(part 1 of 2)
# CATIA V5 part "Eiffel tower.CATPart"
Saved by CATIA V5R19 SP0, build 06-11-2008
Part number: Eiffel tower
Bounding box of the stored display mesh (mm): x -48.5 to 48.5, y -48.5 to 48.5, z 0 to 240.712
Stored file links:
  C:\Documents and Settings\jcerki\Desktop\Eiffel Tower\Eiffel tower.CATPart
  C:\Program Files\Dassault Systemes\B19\intel_a\startup\materials\Catalog.CATMaterial
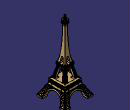
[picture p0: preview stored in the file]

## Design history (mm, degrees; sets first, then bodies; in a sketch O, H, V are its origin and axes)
Sketch1 on xy-plane, origin (0, 0, 0), H (1, 0, 0), V (0, 1, 0)
  line L1 (48.5, 48.5) -> (-48.5, 48.5)
  line L2 (-48.5, 48.5) -> (-48.5, -48.5)
  line L3 (-48.5, -48.5) -> (48.5, -48.5)
  point P4 (48.5, -48.5)
  line L4 (48.5, 48.5) -> (48.5, -48.5)
  point P5 (48.5, -48.5)
  horizontal: L1 H, L3 H
  vertical: L2 V, L4 V
  coincidence: P4 P5
Pad1: profile Sketch1, direction (0, 0, 1), length 6
Sketch2 on Plane2, origin (0, 0, 51.21), H (1, 0, 0), V (0, 1, 0)
  line L1 (27.9, -27.9) -> (27.9, 27.9)
  point P1 (27.9, -27.9)
  point P2 (27.9, 27.9)
  reference projected line E1 (27.9, -27.9) -> (27.9, 27.9) from edge [face of Pad4 from Sketch4.L2 | end face of Pad4]
  reference projected point E2 (27.9, -27.9) from vertex [face of Pad4 from Sketch4.L2 | end face of Pad4 | face of Pad4 from Sketch4.L1]
  reference projected point E3 (27.9, 27.9) from vertex [end face of Pad4 | face of Pad4 from Sketch4.L3 | face of Pad4 from Sketch4.L2]
  line L2 (27.9, -27.9) -> (-27.9, -27.9)
  line L3 (-27.9, -27.9) -> (-27.9, 27.9)
  line L4 (27.9, 27.9) -> (-27.9, 27.9)
  vertical: L1 V, L3 V
  coincidence: L1 E1, P1 E2, P2 E3
  horizontal: L2 H, L4 H
Pad2: profile Sketch2, direction (0, 0, 1), length 1.8
CloseSurface1: CloseElement Join4
Sketch3 on end face of Pad11, origin (0, 0, 230.712), H (1, 0, 0), V (0, 1, 0)
  line L1 (-2.12, -2.12) -> (2.12, -2.12)
  line L2 (2.12, -2.12) -> (2.12, 2.12)
  line L3 (2.12, 2.12) -> (-2.12, 2.12)
  line L4 (-2.12, 2.12) -> (-2.12, -2.12)
  horizontal: L1 H, L3 H
  vertical: L2 V, L4 V
Pad3: profile Sketch3, direction (0, 0, 1), length 10
Sketch4 on Plane1, origin (0, 0, 41.21), H (1, 0, 0), V (0, 1, 0)
  line L1 (-27.9, -27.9) -> (27.9, -27.9)
  line L2 (27.9, -27.9) -> (27.9, 27.9)
  line L3 (27.9, 27.9) -> (-27.9, 27.9)
  line L4 (-27.9, 27.9) -> (-27.9, -27.9)
  horizontal: L1 H, L3 H
  vertical: L2 V, L4 V
Pad4: profile Sketch4, direction (0, 0, 1), length 6.2
Fillet1: radius 0.2, on edge [face of Pad13 from Sketch22.A1 | face of Pad14]; edge [face of Pad14 | face of Pad13 from Sketch22.A1]; edge [face of CircPattern5 | face of CircPattern5] (x6); face of CircPattern3 (x10); edge [face of CircPattern3 | face of CircPattern3]; end face of Pad9 (x4); face of Pad9 from Sketch18.L3; face of Pad9 from Sketch18.L4; face of Pad9 from Sketch18.L1; face of Pad9 from Sketch18.L2; start face of Pad12; end face of Pad8; edge [start face of Pad8 | face of Pad8 from Sketch16.L3]; edge [start face of Pad8 | face of Pad8 from Sketch16.L2]; edge [start face of Pad8 | face of Pad8 from Sketch16.L4]; edge [start face of Pad8 | face of Pad8 from Sketch16.L1]
Body1 (main body)
  Plane1: type Offset, Offset 41.21, RefPlane xy-plane
  Fillet2: radius 1, on end face of Pad1
  AxisSystem1: origin (0, 0, 0), X (1, 0, 0), Y (0, 1, 0), Z (0, 0, 1)
  Plane2: type Offset, Offset 10, RefPlane Plane1
  Line1: type PtPt, SecondPoint vertex [face of Fillet2 | face of Fillet2 | end face of Pad1], FirstPoint vertex [face of Pad4 from Sketch4.L4 | start face of Pad4 | face of Pad4 from Sketch4.L1]
  Line2: type PtPt, SecondPoint vertex [end face of Pad1 | face of Fillet2 | face of Fillet2], FirstPoint vertex [face of Pad4 from Sketch4.L1 | start face of Pad4 | face of Pad4 from Sketch4.L2]
  Line3: type PtPt, SecondPoint vertex [face of Fillet2 | end face of Pad1 | face of Fillet2], FirstPoint vertex [face of Pad4 from Sketch4.L4 | start face of Pad4 | face of Pad4 from Sketch4.L3]
  Line4: type PtPt, SecondPoint vertex [face of Fillet2 | face of Fillet2 | end face of Pad1], FirstPoint vertex [face of Pad4 from Sketch4.L3 | start face of Pad4 | face of Pad4 from Sketch4.L2]
  Fill1: Boundary (edge [start face of Pad4 | face of Pad4 from Sketch4.L3]; Line4; edge [face of Fillet2 | end face of Pad1]; Line3)
  Fill2: Boundary (edge [face of Fillet2 | end face of Pad1]; Line4; edge [start face of Pad4 | face of Pad4 from Sketch4.L2]; Line2)
  Fill3: Boundary (Line2; edge [start face of Pad4 | face of Pad4 from Sketch4.L1]; Line1; edge [face of Fillet2 | end face of Pad1])
  Fill4: Boundary (edge [start face of Pad4 | face of Pad4 from Sketch4.L4]; Line3; edge [face of Fillet2 | end face of Pad1]; Line1)
  Join1: Elements (Fill3; Fill4; Fill1; Fill2)
  CloseSurface2: CloseElement Join1
  Sketch5 on face of Pad1 from Sketch1.L3, origin (0, -48.5, 0), H (1, 0, 0), V (0, 0, 1)
    arc A1 centre (0, 0) radius 30 from (29.3939, 6) to (-29.3939, 6) ccw
    line L1 (29.3939, 6) -> (29.3939, 0)
    point P3 (29.3939, 0)
    line L2 (-29.3939, 6) -> (-29.3939, 0)
    point P4 (-29.3939, 0)
    line L3 (29.3939, 0) -> (-29.3939, 0)
    coincidence: P3 H, P4 H
    vertical: L1 V, L2 V
    horizontal: L3 H
  Pocket1: profile Sketch5, direction (0, 1, 0), through (limit type 6)
  Sketch6 on face of Pad1 from Sketch1.L4, origin (48.5, 0, 0), H (0, 1, 0), V (0, 0, 1)
    arc A1 centre (0, 0) radius 30 from (29.3939, 6) to (-29.3939, 6) ccw
    line L1 (29.3939, 6) -> (29.3939, 0)
    point P3 (29.3939, 0)
    line L2 (29.3939, 0) -> (-29.3939, 0)
    line L3 (-29.3939, 0) -> (-29.3939, 6)
    coincidence: P3 H
    vertical: L1 V, L3 V
    horizontal: L2 H
  Pocket2: profile Sketch6, direction (-1, 0, 0), through (limit type 3)
  Plane3: type Offset, Offset 1.8, RefPlane Plane2
  Sketch7 on Plane3, origin (0, 0, 53.01), H (1, 0, 0), V (0, 1, 0)
    line L1 (-22.25, -22.25) -> (22.25, -22.25)
    line L2 (22.25, -22.25) -> (22.25, 22.25)
    line L3 (22.25, 22.25) -> (-22.25, 22.25)
    line L4 (-22.25, 22.25) -> (-22.25, -22.25)
    horizontal: L1 H, L3 H
    vertical: L2 V, L4 V
  Pad5: profile Sketch7, direction (0, 0, 1), length 2
  Line5: type PtPt, SecondPoint vertex [face of Pad2 from Sketch2.L2 | end face of Pad2 | face of Pad2 from Sketch2.L3], FirstPoint vertex [face of Pad5 from Sketch7.L4 | end face of Pad5 | face of Pad5 from Sketch7.L1]
  Line6: type PtPt, SecondPoint vertex [face of Pad2 from Sketch2.L2 | face of Pad2 from Sketch2.L1 | end face of Pad2], FirstPoint vertex [face of Pad5 from Sketch7.L2 | end face of Pad5 | face of Pad5 from Sketch7.L1]
  Line7: type PtPt, SecondPoint vertex [end face of Pad2 | face of Pad2 from Sketch2.L1 | face of Pad2 from Sketch2.L4], FirstPoint vertex [face of Pad5 from Sketch7.L2 | end face of Pad5 | face of Pad5 from Sketch7.L3]
  Line8: type PtPt, SecondPoint vertex [end face of Pad2 | face of Pad2 from Sketch2.L4 | face of Pad2 from Sketch2.L3], FirstPoint vertex [end face of Pad5 | face of Pad5 from Sketch7.L3 | face of Pad5 from Sketch7.L4]
  Fill5: Boundary (Line5; edge [face of Pad2 from Sketch2.L2 | end face of Pad2]; Line6; edge [face of Pad5 from Sketch7.L1 | end face of Pad5])
  Fill6: Boundary (Line6; edge [face of Pad2 from Sketch2.L1 | end face of Pad2]; Line7; edge [face of Pad5 from Sketch7.L2 | end face of Pad5])
  Fill7: Boundary (edge [face of Pad5 from Sketch7.L4 | end face of Pad5]; Line8; edge [face of Pad2 from Sketch2.L3 | end face of Pad2]; Line5)
  Fill8: Boundary (Line8; edge [face of Pad5 from Sketch7.L3 | end face of Pad5]; Line7; edge [face of Pad2 from Sketch2.L4 | end face of Pad2])
  Join2: Elements (Fill7; Fill8; Fill6; Fill5)
  CloseSurface3: CloseElement Join2
  Plane4: type Offset, Offset 0, RefPlane face of CloseSurface3, reversed
  Plane5: type Offset, Offset 35.7, RefPlane Plane4, reversed
  Sketch8 on Plane5, origin (0, 0, 90.71), H (1, 0, 0), V (0, -1, 0)
    line L1 (-14, 14) -> (14, 14)
    line L2 (-14, 14) -> (-14, -14)
    line L3 (-14, -14) -> (14, -14)
    line L4 (14, -14) -> (14, 14)
    horizontal: L1 H, L3 H
    vertical: L2 V, L4 V
  Line9: type PtPt, SecondPoint vertex [face of CloseSurface3 | face of CloseSurface3 | face of CloseSurface3], FirstPoint vertex [element of Sketch8 | element of Sketch8]
  Line10: type PtPt, SecondPoint vertex [face of CloseSurface3 | face of CloseSurface3 | face of CloseSurface3], FirstPoint vertex [element of Sketch8 | element of Sketch8]
  Line11: type PtPt, SecondPoint vertex [element of Sketch8 | element of Sketch8], FirstPoint vertex [face of CloseSurface3 | face of CloseSurface3 | face of CloseSurface3]
  Line12: type PtPt, SecondPoint vertex [face of CloseSurface3 | face of CloseSurface3 | face of CloseSurface3], FirstPoint vertex [element of Sketch8 | element of Sketch8]
  Pad6: profile Sketch8, direction (0, 0, 1), length 4
  Fill9: Boundary (Line10; edge [face of Pad6 from Sketch8.L4 | start face of Pad6]; Line9; edge [face of CloseSurface3 | face of CloseSurface3])
  Fill10: Boundary (Line9; edge [face of Pad6 from Sketch8.L1 | start face of Pad6]; Line12; edge [face of CloseSurface3 | face of CloseSurface3])
  Fill11: Boundary (Line12; edge [face of Pad6 from Sketch8.L2 | start face of Pad6]; Line11; edge [face of CloseSurface3 | face of CloseSurface3])
  Fill12: Boundary (edge [face of Pad6 from Sketch8.L3 | start face of Pad6]; Line10; edge [face of CloseSurface3 | face of CloseSurface3]; Line11)
  Join3: Elements (Fill11; Fill12; Fill9; Fill10)
  CloseSurface4: CloseElement Join3
  Plane6: type Offset, Offset 4, RefPlane Plane5, reversed
  Sketch9 on Plane6, origin (0, 0, 94.71), H (1, 0, 0), V (0, -1, 0)
    line L1 (-15.85, 15.85) -> (15.85, 15.85)
    line L2 (15.85, 15.85) -> (15.85, -15.85)
    line L3 (15.85, -15.85) -> (-15.85, -15.85)
    line L4 (-15.85, -15.85) -> (-15.85, 15.85)
    horizontal: L1 H, L3 H
    vertical: L2 V, L4 V
  Pad7: profile Sketch9, direction (0, 0, 1), length 6.7
  Plane7: type Offset, Offset 1.8, RefPlane Plane6, reversed
  Sketch10 on Plane7, origin (0, 0, 96.51), H (1, 0, 0), V (0, -1, 0)
    line L1 (-14, 14) -> (14, 14)
    line L2 (-14, 14) -> (-14, -14)
    line L3 (-14, -14) -> (14, -14)
    line L4 (14, -14) -> (14, 14)
    point P5 (15.85, 15.85)
    reference projected line E1 (15.85, 15.85) -> (-15.85, 15.85) from edge [face of Pad7 from Sketch9.L1 | start face of Pad7]
    line L5 (15.85, 15.85) -> (-15.85, 15.85)
    point P6 (-15.85, 15.85)
    reference projected line E2 (-15.85, 15.85) -> (-15.85, -15.85) from edge [face of Pad7 from Sketch9.L4 | start face of Pad7]
    line L6 (15.85, 15.85) -> (15.85, -15.85)
    line L7 (15.85, -15.85) -> (-15.85, -15.85)
    line L8 (-15.85, -15.85) -> (-15.85, 15.85)
    horizontal: L1 H, L3 H, L5 H, L7 H
    vertical: L2 V, L4 V, L6 V, L8 V
    coincidence: P5 E1, P6 E2
  Pocket3: profile Sketch10, direction (0, 0, 1), length 2.5
  Sketch11 on end face of Pad7, origin (0, 0, 101.41), H (1, 0, 0), V (0, 1, 0)
    line L1 (13, 13) -> (-13, 13)
    line L2 (13, 13) -> (13, -13)
    line L3 (13, -13) -> (-13, -13)
    line L4 (-13, 13) -> (-13, -13)
    horizontal: L1 H, L3 H
    vertical: L2 V, L4 V
  Plane8: type Offset, Offset 114, RefPlane end face of Pad7, reversed
  Plane9: type Offset, Offset 4, RefPlane Plane8
  Plane10: type Offset, Offset 19, RefPlane end face of Pad7, reversed
  Sketch12 on Plane10, origin (0, 0, 120.41), H (1, 0, 0), V (0, -1, 0)
    line L1 (-9.1, 9.1) -> (9.1, 9.1)
    line L2 (9.1, 9.1) -> (9.1, -9.1)
    line L3 (9.1, -9.1) -> (-9.1, -9.1)
    line L4 (-9.1, 9.1) -> (-9.1, -9.1)
    horizontal: L1 H, L3 H
    vertical: L2 V, L4 V
  Plane11: type Offset, Offset 50, RefPlane end face of Pad7, reversed
  Sketch13 on Plane11, origin (0, 0, 151.41), H (1, 0, 0), V (0, -1, 0)
    line L1 (-6, 6) -> (6, 6)
    line L2 (-6, 6) -> (-6, -6)
    line L3 (-6, -6) -> (6, -6)
    line L4 (6, -6) -> (6, 6)
    horizontal: L1 H, L3 H
    vertical: L2 V, L4 V
  Sketch14 on Plane9, origin (0, 0, 211.41), H (1, 0, 0), V (0, -1, 0)
    line L1 (-4.75, 4.75) -> (4.75, 4.75)
    line L2 (-4.75, 4.75) -> (-4.75, -4.75)
    line L3 (-4.75, -4.75) -> (4.75, -4.75)
    line L4 (4.75, -4.75) -> (4.75, 4.75)
    horizontal: L1 H, L3 H
    vertical: L2 V, L4 V
  Sketch15 on Plane8, origin (0, 0, 215.41), H (1, 0, 0), V (0, -1, 0)
    line L1 (-5.5, 5.5) -> (5.5, 5.5)
    line L2 (5.5, 5.5) -> (5.5, -5.5)
    line L3 (-5.5, 5.5) -> (-5.5, -5.5)
    line L4 (-5.5, -5.5) -> (5.5, -5.5)
    horizontal: L1 H, L4 H
    vertical: L2 V, L3 V
  Line13: type PtDir, Direction Plane9, Start 0, End 30, RefPoint vertex [element of Sketch14 | element of Sketch14]
  Point1: (0, 0, 0), relative to vertex of Line13, in AxisSystem1
  Curve1: Elements (vertex [element of Sketch11 | element of Sketch11]; vertex [element of Sketch12 | element of Sketch12]; vertex [element of Sketch13 | element of Sketch13]; Point1; vertex [element of Sketch14 | element of Sketch14])
  Fill13: Boundary Sketch14
  CircPattern1: of Point1, instances 4, angular step 90, axis from edge [ZX plane of AxisSystem1 | YZ plane of AxisSystem1]
  Curve2: Elements (vertex [element of Sketch11 | element of Sketch11]; vertex [element of Sketch12 | element of Sketch12]; vertex [element of Sketch13 | element of Sketch13]; vertex of CircPattern1; vertex [element of Sketch14 | element of Sketch14])
  Curve3: Elements (vertex [element of Sketch11 | element of Sketch11]; vertex [element of Sketch12 | element of Sketch12]; vertex [element of Sketch13 | element of Sketch13]; vertex of CircPattern1; vertex [element of Sketch14 | element of Sketch14])
  Curve4: Elements (vertex [element of Sketch14 | element of Sketch14]; vertex of CircPattern1; vertex [element of Sketch13 | element of Sketch13]; vertex [element of Sketch12 | element of Sketch12]; vertex [element of Sketch11 | element of Sketch11])
  Line14: type PtPt, SecondPoint vertex of Curve2, FirstPoint vertex of Curve1
  Line15: type PtPt, SecondPoint vertex of Curve3, FirstPoint vertex of Curve2
  Line16: type PtPt, SecondPoint vertex of Curve4, FirstPoint vertex of Curve1
  Line17: type PtPt, SecondPoint vertex of Curve4, FirstPoint vertex of Curve3
  Fill14: Boundary (Line14; Curve2; edge of Fill13; Curve1)
  Fill15: Boundary (Line16; edge of Fill14; edge of Fill13; Curve4)
  Fill16: Boundary (Line17; edge of Fill15; edge of Fill13; Curve3)
  Fill17: Boundary (Line15; edge of Fill16; edge of Fill13; edge of Fill14)
  Join4: Elements (Fill16; Fill17; Fill14; Fill15)
  Fill18: Boundary Sketch15
  Line18: type PtPt, SecondPoint vertex [element of Sketch15 | element of Sketch15], FirstPoint vertex [face of Fill15 | face of Fill16]
  Line19: type PtPt, SecondPoint vertex [element of Sketch15 | element of Sketch15], FirstPoint vertex [face of CloseSurface1 | face of CloseSurface1 | face of CloseSurface1]
  Line20: type PtPt, SecondPoint vertex [element of Sketch15 | element of Sketch15], FirstPoint vertex [face of CloseSurface1 | face of CloseSurface1 | face of CloseSurface1]
  Line21: type PtPt, SecondPoint vertex [element of Sketch15 | element of Sketch15], FirstPoint vertex [face of CloseSurface1 | face of CloseSurface1 | face of CloseSurface1]
  Line22: type PtPt, SecondPoint vertex of Line19, FirstPoint vertex of Line21
  Line23: type PtPt, SecondPoint vertex of Line20, FirstPoint vertex of Line21
  Line24: type PtPt, SecondPoint vertex of Line18, FirstPoint vertex of Line20
  Line25: type PtPt, SecondPoint vertex of Line18, FirstPoint vertex of Line19
  Fill19: Boundary (Line22; Line19; edge [face of CloseSurface1 | face of CloseSurface1]; Line21)
  Fill20: Boundary (edge [face of CloseSurface1 | face of CloseSurface1]; Line19; Line25; Line18)
  Fill21: Boundary (Line21; Line23; Line20; edge [face of CloseSurface1 | face of CloseSurface1])
  Fill22: Boundary (Line20; Line24; Line18; edge [face of CloseSurface1 | face of CloseSurface1])
  Join5: Elements (Fill22; Fill21; Fill19; Fill20)
  CloseSurface5: CloseElement Join5
  Sketch16 on face of CloseSurface5, origin (0, 0, 215.41), H (1, 0, 0), V (0, 1, 0)
    line L1 (-7.35, -7.35) -> (7.35, -7.35)
    line L2 (7.35, -7.35) -> (7.35, 7.35)
    line L3 (7.35, 7.35) -> (-7.35, 7.35)
    line L4 (-7.35, 7.35) -> (-7.35, -7.35)
    horizontal: L1 H, L3 H
    vertical: L2 V, L4 V
  Pad8: profile Sketch16, direction (0, 0, 1), length 4.1
  Fillet3: radius 1.5, on edge [face of Pad8 from Sketch16.L2 | face of Pad8 from Sketch16.L1]; edge [face of Pad8 from Sketch16.L1 | face of Pad8 from Sketch16.L4]; edge [face of Pad8 from Sketch16.L4 | face of Pad8 from Sketch16.L3]; edge [face of Pad8 from Sketch16.L3 | face of Pad8 from Sketch16.L2]
  Fillet4: radius 2, on edge [start face of Pad8 | face of CloseSurface5] (x2); edge [face of CloseSurface5 | start face of Pad8] (x2)
  Fillet5: radius 29, on edge [face of CloseSurface5 | face of CloseSurface1] (x2); edge [face of CloseSurface1 | face of CloseSurface5] (x2)
  Sketch17 on face of Pad8 from Sketch16.L1, origin (0, -7.35, 0), H (1, 0, 0), V (0, 0, 1)
    line L1 (-5, 216.5) -> (5, 216.5)
    line L2 (5, 216.5) -> (5, 218.5)
    line L3 (5, 218.5) -> (-5, 218.5)
    line L4 (-5, 218.5) -> (-5, 216.5)
    horizontal: L1 H, L3 H
    vertical: L2 V, L4 V
  Pocket4: profile Sketch17, direction (0, 1, 0), length 1
  CircPattern2: of Pocket4, instances 4, angular step 90, axis from edge [ZX plane of AxisSystem1 | YZ plane of AxisSystem1]
  Sketch18 on end face of Pad8, origin (0, 0, 219.51), H (1, 0, 0), V (0, 1, 0)
    line L1 (-6, -6) -> (6, -6)
    line L2 (6, -6) -> (6, 6)
    line L3 (6, 6) -> (-6, 6)
    line L4 (-6, 6) -> (-6, -6)
    horizontal: L1 H, L3 H
    vertical: L2 V, L4 V
  Pad9: profile Sketch18, direction (0, 0, 1), length 3
  Sketch19 on end face of Pad9, origin (0, 0, 222.51), H (1, 0, 0), V (0, 1, 0)
    circle A1 centre (0, 0) radius 5
    point P1 (5, 0)
    coincidence: A1 P1, P1 H
  Pad10: profile Sketch19, direction (0, 0, 1), length 3
  Sketch20 on end face of Pad10, origin (0, 0, 225.51), H (1, 0, 0), V (0, 1, 0)
    circle A1 centre (0, 0) radius 3
    point P1 (-3, 0)
    coincidence: A1 P1, P1 H
  Pad11: profile Sketch20, direction (0, 0, 1), length 5.202
  Draft1: Angle 3, SupportToDraft (face of Pad3 from Sketch3.L1; face of Pad3 from Sketch3.L2; face of Pad3 from Sketch3.L4; face of Pad3 from Sketch3.L3), PullDir end face of Pad11, Neutral end face of Pad11
  Fillet6: radius 0.5, on edge [face of Pad3 from Sketch3.L4 | face of Pad3 from Sketch3.L1]; edge [face of Pad3 from Sketch3.L3 | face of Pad3 from Sketch3.L4]; edge [face of Pad3 from Sketch3.L3 | face of Pad3 from Sketch3.L2]; edge [face of Pad3 from Sketch3.L2 | face of Pad3 from Sketch3.L1]
  Fillet7: radius 1, on end face of Pad3
  Fillet8: radius 0.2, on edge [face of Pad11 from Sketch20.A1 | end face of Pad11]
  Fillet9: radius 0.1, on edge [face of Pad3 from Sketch3.L4 | end face of Pad11]
  Sketch21 on end face of Pad9, origin (0, 0, 222.51), H (1, 0, 0), V (0, 1, 0)
    line L1 (0.7071, 0.7071) -> (6.5071, -5.0929)
    line L2 (-0.7071, -0.7071) -> (5.0929, -6.5071)
    arc A1 centre (5.8, -5.8) radius 1 from (5.0929, -6.5071) to (6.5071, -5.0929) ccw
    line L3 (-0.7071, -0.7071) -> (0.7071, 0.7071)
    tangency: A1 L1
    perpendicularity: L3 L1
  Pad12: profile Sketch21, direction (0, 0, 1), up to end face of Pad10
  CircPattern3: of Pad12, instances 4, angular step 90, axis from edge [ZX plane of AxisSystem1 | YZ plane of AxisSystem1]
  Point2: type Center, Curve edge [face of CircPattern3 | face of Pad11 from Sketch20.A1]
  Point3: type Center, Curve edge [face of CircPattern3 | face of CircPattern3]
  Line26: type PtPt, SecondPoint Point3, FirstPoint Point2
  Point4: type Center, Curve edge [face of Fillet8 | end face of Pad11]
  Line27: type PtPt, SecondPoint Point4, FirstPoint Point2
  Line28: type PtPt, SecondPoint Point3, FirstPoint Point2
  Plane12: type 3Points, Element1 Point2, Element2 Point4, Element3 Point3
  Line29: type PtDir, Direction Line28, Start 0, End 3, RefPoint Point4
  Sketch22 on Plane12, origin (0, 0, 0), H (0.7071, -0.7071, 0), V (0, 0, 1)
    line L1 (-3, 230.712) -> (-3, 225.51)
    point P1 (-3, 230.712)
    reference projected point E1 (-3, 230.712) from vertex of Line29
    line L2 (-3, 225.51) -> (-8.2024, 225.51)
    point P3 (-8.2024, 225.51)
    reference projected point E2 (-8.2024, 225.51) from Point3
    arc A1 centre (-3, 225.51) radius 5.202 from (-3, 230.712) to (-8.202, 225.51) ccw
    point P4 (-8.202, 225.51)
    vertical: L1 V
    coincidence: P1 E1, P3 E2, P4 L2
    horizontal: L2 H
  Pad13: profile Sketch22, direction (-0.7071, -0.7071, 0), length 1, opposite side length 1
  Sketch23 on face of Pad13 from Sketch22.L1, origin (-2.1213, 2.1213, 0), H (0.7071, 0.7071, 0), V (0, 0, 1)
    line L1 (0, 230.712) -> (1, 230.712)
    point P1 (0, 230.712)
    reference intersected point E1 (0, 230.712) from end face of Pad11
    line L2 (1, 230.712) -> (1, 225.51)
    point P3 (1, 225.51)
    reference projected line E2 (-1, 225.51) -> (-4.899, 225.51) from edge [face of Pad10 from Sketch19.A1 | face of CircPattern3]
    line L3 (1, 225.51) -> (-1, 225.51)
    line L4 (-1, 225.51) -> (-1, 230.712)
    point P5 (-1, 230.712)
    line L5 (-1, 230.712) -> (0, 230.712)
    coincidence: P1 V, L1 E1, P3 E2, P5 L1
    horizontal: L1 H, L3 H, L5 H
    vertical: L2 V, L4 V
  Pad14: profile Sketch23, direction (0.7071, -0.7071, 0), length 0.5
  CircPattern4: of Pad14, instances 4, angular step 90, axis from Line27
  CircPattern5: of Pad13, instances 4, angular step 90, axis from Line27
  Fillet10: radius 0.2, on edge [face of Pad14 | face of Pad11 from Sketch20.A1]; edge [face of Pad11 from Sketch20.A1 | face of CircPattern5] (x3); edge [face of CircPattern5 | face of Pad11 from Sketch20.A1] (x3); edge [face of Pad11 from Sketch20.A1 | face of Pad14]
  Fillet11: radius 0.2, on end face of Pocket4; face of CircPattern2 (x3)
  Fillet12: radius 0.2, on edge [face of Pad8 from Sketch16.L4 | face of CircPattern2] (x4); edge [face of Pad8 from Sketch16.L1 | face of Pocket4 from Sketch17.L1]; edge [face of Pad8 from Sketch16.L1 | face of Pocket4 from Sketch17.L2]; edge [face of Pad8 from Sketch16.L1 | face of Pocket4 from Sketch17.L3]; edge [face of Pad8 from Sketch16.L1 | face of Pocket4 from Sketch17.L4]; edge [face of Pad8 from Sketch16.L2 | face of CircPattern2] (x4); edge [face of Pad8 from Sketch16.L3 | face of CircPattern2] (x4)
  Sketch24 on face of Pad7 from Sketch9.L1, origin (0, -15.85, 0), H (1, 0, 0), V (0, 0, 1)
    offset curve E1 from edge of Curve4
    offset curve E2 from edge of Curve4
    offset curve E3 from edge of Curve2
    offset curve E4 from edge of Curve2
    line L1 (-6.2958, 101.41) -> (6.2958, 101.41)
    reference intersected line E5 (-15.85, 101.41) -> (15.85, 101.41) from end face of Pad7
    horizontal: L1 H
    coincidence: L1 E5
  Pocket5: profile Sketch24, direction (0, 1, 0), through (limit type 6)
  CircPattern6: of Pocket5, instances 2, angular step 90, axis from edge [ZX plane of AxisSystem1 | YZ plane of AxisSystem1]
  Sketch25 on end face of Pad4, origin (0, 0, 47.41), H (1, 0, 0), V (0, 1, 0)
    line L1 (1, -26) -> (1, -27)
    line L2 (1, -27) -> (2, -27)
    line L3 (2, -27) -> (2, -24)
    point P6 (-2, -27)
    line L4 (-2, -27) -> (-2, -24)
    point P7 (-2, -27)
    point P8 (-1, -27)
    line L5 (-1, -27) -> (-2, -27)
    point P9 (-1, -27)
    line L6 (-1, -26) -> (-1, -27)
    line L7 (2, -24) -> (-2, -24)
    line L8 (1, -26) -> (-1, -26)
    vertical: L1 V, L3 V
    horizontal: L2 H, L7 H, L8 H
    coincidence: P6 P7, P8 P9
  Pad15: profile Sketch25, direction (0, 0, 1), up to the existing solid (limit type 2)
  RectPattern1: of Pad15, direction 1 instances 4, spacing 7, along face of Pad4 from Sketch4.L1 reversed
  RectPattern2: of Pad15, direction 1 instances 4, spacing 7, along face of Pad4 from Sketch4.L1
  CircPattern7: of RectPattern1, instances 4, angular step 90, axis from edge [ZX plane of AxisSystem1 | YZ plane of AxisSystem1]
  CircPattern8: of RectPattern2, instances 4, angular step 90, axis from edge [ZX plane of AxisSystem1 | YZ plane of AxisSystem1]
  Sketch26 on face of Pad2 from Sketch2.L2, origin (0, -27.9, 0), H (1, 0, 0), V (0, 0, 1)
    line L1 (-13, 55.01) -> (13, 55.01)
    reference projected line E1 (-22.25, 55.01) -> (22.25, 55.01) from edge [face of CloseSurface3 | face of CloseSurface4]
    line L2 (-7.5, 85.71) -> (7.5, 85.71)
    reference projected line E2 (14, 90.71) -> (-14, 90.71) from edge [face of Pad6 from Sketch8.L1 | face of CloseSurface4]
    line L3 (13, 55.01) -> (7.5, 85.71)
    line L4 (-13, 55.01) -> (-7.5, 85.71)
    distance L2 E2 = 5
    horizontal: L1 H, L2 H
    coincidence: L1 E1
  Pocket6: profile Sketch26, direction (0, 1, 0), through (limit type 6)
  CircPattern9: of Pocket6, instances 2, angular step 90, axis from edge [ZX plane of AxisSystem1 | YZ plane of AxisSystem1]
  Fillet13: radius 1.8, on edge [start face of Pad7 | face of Pad6 from Sketch8.L1]; edge [start face of Pad7 | face of Pad6 from Sketch8.L2]; edge [start face of Pad7 | face of Pad6 from Sketch8.L4]; edge [start face of Pad7 | face of Pad6 from Sketch8.L3]
  Fillet14: radius 2.5, on edge [face of Pocket6 from Sketch26.L4 | face of CircPattern9] (x2); edge [face of CircPattern9 | face of CircPattern9] (x8); edge [face of CircPattern9 | face of Pocket6 from Sketch26.L3] (x2); edge [face of Pocket6 from Sketch26.L3 | face of CircPattern9] (x2); edge [face of CircPattern9 | face of Pocket6 from Sketch26.L4] (x2)
  Fillet15: radius 2.5, on edge [face of CircPattern6 | face of Pocket5 from Sketch24.E2] (x2); edge [face of Pocket5 from Sketch24.E4 | face of CircPattern6] (x2); edge [face of CircPattern6 | face of CircPattern6] (x4)
  Sketch27 on yz-plane, origin (0, 0, 0), H (0, 1, 0), V (0, 0, 1)
    point P1 (0, 145.8284)
    line L1 (2.935, 117.9213) -> (0, 144.8823)
    line L2 (-2.935, 117.9213) -> (0, 144.8823)
    arc A1 centre (0, 117.3) radius 3 from (2.935, 117.9213) to (-2.935, 117.9213) ccw
    point P4 (0, 117.3)
    coincidence: P1 V, P4 V
  Pad16: profile Sketch27, direction (1, 0, 0), length 11
  Line30: type PtPt, SecondPoint vertex [face of CloseSurface1 | face of CloseSurface1 | face of CircPattern6], FirstPoint vertex [face of CloseSurface1 | face of CloseSurface1 | face of CircPattern6]
  Fill23: Boundary (Line30; edge [face of CloseSurface1 | face of CloseSurface1]; edge [face of Fillet5 | face of CloseSurface1]; edge [face of CloseSurface1 | face of CloseSurface1])
  Split1: SplitPlane Fill23
  Line31: type PtPt, SecondPoint vertex [face of Fillet15 | face of Fillet15 | face of CircPattern6 | face of Pocket5 from Sketch24.E4], FirstPoint vertex [face of Fillet15 | face of Fillet15 | face of CircPattern6 | face of Pocket5 from Sketch24.E4]
  Line32: type PtPt, SecondPoint vertex [face of Pocket5 from Sketch24.E2 | face of CloseSurface1 | face of Pocket5 from Sketch24.E4], FirstPoint vertex [face of Pocket5 from Sketch24.E2 | face of CloseSurface1 | face of Pocket5 from Sketch24.E4]
  Fill24: Boundary (Line32; edge [face of CloseSurface1 | face of Pocket5 from Sketch24.E4]; edge [face of Fillet15 | face of Pocket5 from Sketch24.E4]; Line31; edge [face of Fillet15 | face of Pocket5 from Sketch24.E4]; edge [face of Pocket5 from Sketch24.E4 | face of CloseSurface1])
  Split2: SplitPlane Fill24
  Pad17: profile Sketch27, direction (-1, 0, 0), length 11
  Line33: type PtPt, SecondPoint vertex [face of Split2 | face of CloseSurface1 | face of Pocket5 from Sketch24.E2], FirstPoint vertex [face of Split2 | face of CloseSurface1 | face of Pocket5 from Sketch24.E2]
  Line34: type PtPt, SecondPoint vertex [face of CircPattern6 | face of CloseSurface1 | face of CloseSurface1], FirstPoint vertex [face of CircPattern6 | face of CloseSurface1 | face of CloseSurface1]
  Line35: type PtPt, SecondPoint vertex [face of Fillet15 | face of CloseSurface1 | face of Pocket5 from Sketch24.E2], FirstPoint vertex [face of Fillet15 | face of CloseSurface1 | face of Pocket5 from Sketch24.E2]
  Fill25: Boundary (Line35; edge [face of CloseSurface1 | face of Pocket5 from Sketch24.E2]; Line33; edge [face of Pocket5 from Sketch24.E2 | face of CloseSurface1])
  Fill26: Boundary (edge [face of CloseSurface1 | face of CloseSurface1]; Line34; edge [face of CloseSurface1 | face of CloseSurface1]; edge [face of CloseSurface1 | face of Fillet5])
  Split3: SplitPlane Fill25
  Split4: SplitPlane Fill26
  Sketch28 on zx-plane, origin (0, 0, 0), H (-1, 0, 0), V (0, 0, 1)
    point P1 (0, 145.8284)
    line L1 (2.935, 117.9213) -> (0, 144.8823)
    line L2 (-2.935, 117.9213) -> (0, 144.8823)
    arc A1 centre (0, 117.3) radius 3 from (2.935, 117.9213) to (-2.935, 117.9213) ccw
  Pad18: profile Sketch28, direction (0, 1, 0), length 11
  Line36: type PtPt, SecondPoint vertex [face of Split1 | face of CircPattern6 | face of CloseSurface1], FirstPoint vertex [face of CircPattern6 | face of Split4 | face of CloseSurface1]
  Line37: type PtPt, SecondPoint vertex [face of Fillet15 | face of CircPattern6 | face of Split1], FirstPoint vertex [face of Fillet15 | face of Split4 | face of CircPattern6]
  Fill27: Boundary (Line36; edge [face of CloseSurface1 | face of Split4]; edge [face of CloseSurface1 | face of Fillet5]; edge [face of Split1 | face of CloseSurface1])
  Line38: type PtPt, SecondPoint vertex [face of Pad18 from Sketch28.L2 | face of Pad18 from Sketch28.L1 | face of CloseSurface1], FirstPoint vertex [face of CloseSurface1 | face of Split2 | face of Split3]
  Point5: type OnCurve, Support Line38, Ratio 0.5
  Line39: type PtDir, Direction Line37, Start 0, End 11, RefPoint Point5
  Line40: type PtDir, Direction Line39, Start 0, End 11, RefPoint Point5
  Split5: SplitPlane Fill27
  Pad19: profile Sketch28, direction (0, -1, 0), length 11
  Line41: type PtPt, SecondPoint vertex [face of CircPattern6 | face of CloseSurface1 | face of Split4], FirstPoint vertex [face of CircPattern6 | face of CloseSurface1 | face of Split1]
  Line42: type PtPt, SecondPoint vertex [face of Fillet15 | face of CircPattern6 | face of Split4], FirstPoint vertex [face of Fillet15 | face of CircPattern6 | face of Split1]
  Fill28: Boundary (Line41; edge [face of CloseSurface1 | face of Split1]; edge [face of Fillet5 | face of CloseSurface1]; edge [face of CloseSurface1 | face of Split4])
  Split6: SplitPlane Fill28
  Sketch29 on yz-plane, origin (0, 0, 0), H (0, 1, 0), V (0, 0, 1)
    circle A1 centre (0, 117.3) radius 3
    point P1 (0, 117.3)
    reference projected arc E1 centre (0, 117.3) radius 3 from (2.8797, 118.1411) to (-2.8797, 118.1412) ccw from edge [face of Pad16 from Sketch27.A1 | face of Split1]
    coincidence: P1 V, A1 E1
  Pocket7: profile Sketch29, direction (-1, 0, 0), through (limit type 6), opposite side through (limit type 6)
  Sketch30 on face of CloseSurface2, origin (0, -38.813, 21.6056), H (1, 0, 0), V (0, 0.4864, 0.8737)
    line L1 (31.8928, -17.8606) -> (14.8722, 22.4371)
    point P1 (31.8928, -17.8606)
    point P2 (14.8722, 22.4371)
    reference projected line E1 (-47.5, -17.8606) -> (47.5, -17.8606) from edge [face of Fillet2 | face of CloseSurface2]
    reference projected line E2 (27.9, 22.4371) -> (-27.9, 22.4371) from edge [face of Pad4 from Sketch4.L1 | face of CloseSurface2]
    line L2 (31.8928, -17.8606) -> (32.8928, -17.8606)
    point P3 (31.8928, -17.8606)
    point P4 (32.8928, -17.8606)
    point P5 (15.8722, 22.4371)
    point P6 (32.8928, -17.8606)
    line L3 (32.8928, -17.8606) -> (15.8722, 22.4371)
    line L4 (14.8722, 22.4371) -> (15.8722, 22.4371)
    reference intersected line E3 through (0, 0) direction (0, 1) from yz-plane
    point P9 (-14.8722, 22.4371)
    point P10 (-31.8928, -17.8606)
    line L5 (-31.8928, -17.8606) -> (-14.8722, 22.4371)
    point P11 (-15.8722, 22.4371)
    point P12 (-32.8928, -17.8606)
    line L6 (-32.8928, -17.8606) -> (-15.8722, 22.4371)
    point P13 (-32.8928, -17.8606)
    point P14 (-31.8928, -17.8606)
    line L7 (-31.8928, -17.8606) -> (-32.8928, -17.8606)
    point P15 (-15.8722, 22.4371)
    point P16 (-14.8722, 22.4371)
    line L8 (-14.8722, 22.4371) -> (-15.8722, 22.4371)
    coincidence: P1 E1, P2 E2, P3 L1, P1 P3, P4 P6
    horizontal: L2 H, L4 H
    symmetry: P2 P9 E3, P1 P10 E3, L1 L5 E3, P5 P11 E3, P6 P12 E3, L3 L6 E3, P4 P13 E3, P3 P14 E3, L2 L7 E3, P5 P15 E3, P2 P16 E3, L4 L8 E3
  Pocket8: profile Sketch30, direction (0, 0.8737, -0.4864), length 0.5
  Sketch31 on face of CloseSurface2, origin (0, -38.813, 21.6056), H (1, 0, 0), V (0, 0.4864, 0.8737)
    arc A1 centre (0, -15.7693) radius 30 from (22.7492, 3.7877) to (-22.7492, 3.7877) ccw
    point P1 (0, -15.7693)
    arc A2 centre (0, -15.7693) radius 31 from (21.6299, 6.4376) to (-21.6299, 6.4376) ccw
    line L1 (21.6299, 6.4376) -> (22.7492, 3.7877)
    reference projected line E1 (14.8722, 22.4371) -> (31.8928, -17.8606) from edge [face of CloseSurface2 | face of Pocket8 from Sketch30.L1]
    reference projected line E2 (14.8722, 22.4371) -> (31.8928, -17.8606) from edge [face of CloseSurface2 | face of Pocket8 from Sketch30.L1]
    point P2 (22.7492, 3.7877)
    point P3 (21.6299, 6.4376)
    reference intersected line E3 through (0, 0) direction (0, 1) from yz-plane
    point P6 (-22.7492, 3.7877)
    point P7 (-21.6299, 6.4376)
    line L2 (-21.6299, 6.4376) -> (-22.7492, 3.7877)
    distance L1 E2 = 0
    coincidence: P1 V
    parallelism: L1 E1
    symmetry: P2 P6 E3, P3 P7 E3, L1 L2 E3
  Pocket9: profile Sketch31, direction (0, 0.8737, -0.4864), length 0.5
  CircPattern10: of Pocket9, instances 4, angular step 90, axis from edge [ZX plane of AxisSystem1 | YZ plane of AxisSystem1]
  CircPattern11: of Pocket8, instances 4, angular step 90, axis from edge [ZX plane of AxisSystem1 | YZ plane of AxisSystem1]
  Sketch32 on face of CloseSurface2, origin (0, -38.813, 21.6056), H (1, 0, 0), V (0, 0.4864, 0.8737)
    point P1 (29.5626, 17.13)
    point P2 (30, 16.2307)
    line L1 (30, 16.2307) -> (29.5626, 17.13)
    reference projected line E1 (27.9, 22.4371) -> (47.5, -17.8606) from edge [face of CloseSurface2 | face of CloseSurface2]
    line L2 (30, 16.2307) -> (0, 16.2307)
    point P3 (0, 16.2307)
    line L3 (29.5626, 17.13) -> (0, 17.13)
    point P4 (0, 17.13)
    point P5 (0, 16.2307)
    point P6 (-30, 16.2307)
    line L4 (-30, 16.2307) -> (0, 16.2307)
    point P7 (-29.5626, 17.13)
    point P8 (-30, 16.2307)
    line L5 (-30, 16.2307) -> (-29.5626, 17.13)
    point P9 (0, 17.13)
    point P10 (-29.5626, 17.13)
    line L6 (-29.5626, 17.13) -> (0, 17.13)
    parallelism: L1 E1
    coincidence: P3 V, P4 V, P3 P5, P4 P9, P6 P8, P7 P10
    horizontal: L2 H, L3 H
    symmetry: P3 P5 V, P2 P6 V, L2 L4 V, P1 P7 V, P2 P8 V, L1 L5 V, P4 P9 V, P1 P10 V, L3 L6 V
  Pocket10: profile Sketch32, direction (0, 0.8737, -0.4864), length 0.5
  CircPattern12: of Pocket10, instances 4, angular step 90, axis from edge [ZX plane of AxisSystem1 | YZ plane of AxisSystem1]
  Sketch33 on face of Pad4 from Sketch4.L1, origin (0, -27.9, 0), H (1, 0, 0), V (0, 0, 1)
    line L1 (-26.9, 42.21) -> (-26.9, 46.41)
    line L2 (-24.4, 46.41) -> (-24.4, 42.21)
    line L3 (-24.4, 42.21) -> (-26.9, 42.21)
    line L4 (-24.4, 46.41) -> (-26.9, 46.41)
    vertical: L1 V
    horizontal: L3 H, L4 H
  Pocket11: profile Sketch33, direction (0, 1, 0), length 0.5
  RectPattern3: of Pocket11, direction 1 instances 17, spacing 3.205, along edge [face of Pad4 from Sketch4.L1 | face of CloseSurface2] reversed
  CircPattern13: of RectPattern3, instances 4, angular step 90, axis from edge [ZX plane of AxisSystem1 | YZ plane of AxisSystem1]
  Fillet16: radius 0.2, on edge [face of Pad4 from Sketch4.L1 | end face of Pad4]; edge [start face of Pad2 | face of Pad2 from Sketch2.L2]; edge [face of Pad2 from Sketch2.L2 | face of CloseSurface3]; edge [face of Pad4 from Sketch4.L2 | end face of Pad4]; edge [start face of Pad2 | face of Pad2 from Sketch2.L1]; edge [face of Pad2 from Sketch2.L1 | face of CloseSurface3]; edge [face of Pad4 from Sketch4.L3 | end face of Pad4]; edge [start face of Pad2 | face of Pad2 from Sketch2.L4]; edge [face of Pad2 from Sketch2.L4 | face of CloseSurface3]; edge [face of Pad4 from Sketch4.L4 | end face of Pad4]; edge [start face of Pad2 | face of Pad2 from Sketch2.L3]; edge [face of Pad2 from Sketch2.L3 | face of CloseSurface3]
  Sketch34 on face of CloseSurface2, origin (0, -38.813, 21.6056), H (1, 0, 0), V (0, 0.4864, 0.8737)
    line L1 (25.8693, 22.4371) -> (45.4693, -17.8606)
    point P1 (25.8693, 22.4371)
    point P2 (45.4693, -17.8606)
    reference projected line E1 (30, 16.2307) -> (29.5626, 17.13) from edge [face of CloseSurface2 | face of Pocket10 from Sketch32.L1]
    reference projected line E2 (30, 16.2307) -> (29.5626, 17.13) from edge [face of CloseSurface2 | face of Pocket10 from Sketch32.L1]
    reference projected line E3 (27.9, 22.4371) -> (-27.9, 22.4371) from edge [face of Pad4 from Sketch4.L1 | face of CloseSurface2]
    reference projected line E4 (-47.5, -17.8606) -> (47.5, -17.8606) from edge [face of Fillet2 | face of CloseSurface2]
    line L2 (25.8693, 22.4371) -> (26.9813, 22.4371)
    point P3 (26.9813, 22.4371)
    line L3 (26.9813, 22.4371) -> (46.5813, -17.8606)
    point P4 (46.5813, -17.8606)
    reference projected line E5 (-47.5, -17.8606) -> (47.5, -17.8606) from edge [face of Fillet2 | face of CloseSurface2]
    line L4 (46.5813, -17.8606) -> (45.4693, -17.8606)
    point P5 (-45.4693, -17.8606)
    point P6 (-25.8693, 22.4371)
    line L5 (-25.8693, 22.4371) -> (-45.4693, -17.8606)
    point P7 (-46.5813, -17.8606)
    point P8 (-26.9813, 22.4371)
    line L6 (-26.9813, 22.4371) -> (-46.5813, -17.8606)
    point P9 (-26.9813, 22.4371)
    point P10 (-25.8693, 22.4371)
    line L7 (-25.8693, 22.4371) -> (-26.9813, 22.4371)
    point P11 (-45.4693, -17.8606)
    point P12 (-46.5813, -17.8606)
    line L8 (-46.5813, -17.8606) -> (-45.4693, -17.8606)
    reference projected line E6 (30, 16.2307) -> (29.5626, 17.13) from edge [face of CloseSurface2 | face of Pocket10 from Sketch32.L1]
    distance L1 E2 = 1
    distance L3 E6 = 0
    parallelism: L1 E1, L3 L1
    coincidence: P1 E3, P2 E4, P4 E5, P5 P11, P6 P10, P7 P12, P8 P9
    horizontal: L2 H, L4 H
    symmetry: P2 P5 V, P1 P6 V, L1 L5 V, P4 P7 V, P3 P8 V, L3 L6 V, P3 P9 V, P1 P10 V, L2 L7 V, P2 P11 V, P4 P12 V, L4 L8 V
  Pocket12: profile Sketch34, direction (0, 0.8737, -0.4864), length 0.5
  CircPattern14: of Pocket12, instances 4, angular step 90, axis from edge [ZX plane of AxisSystem1 | YZ plane of AxisSystem1]
  Sketch35 on face of CloseSurface4, origin (0, -33.1899, 7.6699), H (1, 0, 0), V (0, 0.2252, 0.9743)
    line L1 (12.975, 85.2285) -> (21.225, 48.5877)
    point P1 (12.975, 85.2285)
    point P2 (21.225, 48.5877)
    reference projected line E1 (14, 85.2285) -> (-14, 85.2285) from edge [face of Pad6 from Sketch8.L1 | face of CloseSurface4]
    reference projected line E2 (14, 85.2285) -> (22.25, 48.5877) from edge [face of CloseSurface4 | face of CloseSurface4]
    reference projected line E3 (14, 85.2285) -> (22.25, 48.5877) from edge [face of CloseSurface4 | face of CloseSurface4]
    reference projected line E4 (-22.25, 48.5877) -> (22.25, 48.5877) from edge [face of CloseSurface3 | face of CloseSurface4]
    line L2 (21.225, 48.5877) -> (20.225, 48.5877)
    point P3 (20.225, 48.5877)
    line L3 (20.225, 48.5877) -> (11.975, 85.2285)
    point P4 (11.975, 85.2285)
    line L4 (12.975, 85.2285) -> (11.975, 85.2285)
    point P5 (7.6194, 85.2285)
    point P6 (14.0151, 48.5877)
    line L5 (14.0151, 48.5877) -> (7.6194, 85.2285)
    reference projected line E5 (13, 48.5877) -> (7.5, 80.0968) from edge [face of CloseSurface4 | face of Pocket6 from Sketch26.L3]
    reference projected line E6 (13, 48.5877) -> (7.5, 80.0968) from edge [face of CloseSurface4 | face of Pocket6 from Sketch26.L3]
    reference projected line E7 (14, 85.2285) -> (-14, 85.2285) from edge [face of Pad6 from Sketch8.L1 | face of CloseSurface4]
    reference projected line E8 (-22.25, 48.5877) -> (22.25, 48.5877) from edge [face of CloseSurface3 | face of CloseSurface4]
    line L6 (7.6194, 85.2285) -> (8.6194, 85.2285)
    point P7 (8.6194, 85.2285)
    point P8 (8.6194, 85.2285)
    point P9 (15.0151, 48.5877)
    line L7 (15.0151, 48.5877) -> (8.6194, 85.2285)
    line L8 (14.0151, 48.5877) -> (15.0151, 48.5877)
    point P10 (-7.6194, 85.2285)
    point P11 (-14.0151, 48.5877)
    line L9 (-14.0151, 48.5877) -> (-7.6194, 85.2285)
    point P12 (-8.6194, 85.2285)
    point P13 (-15.0151, 48.5877)
    line L10 (-15.0151, 48.5877) -> (-8.6194, 85.2285)
    reference projected line E9 through (0, 0) direction (0, 1) from edge [ZX plane of AxisSystem1 | YZ plane of AxisSystem1]
    point P16 (-11.975, 85.2285)
    point P17 (-20.225, 48.5877)
    line L11 (-20.225, 48.5877) -> (-11.975, 85.2285)
    point P18 (-21.225, 48.5877)
    point P19 (-12.975, 85.2285)
    line L12 (-12.975, 85.2285) -> (-21.225, 48.5877)
    line L13 (-7.6194, 85.2285) -> (-8.6194, 85.2285)
    line L14 (-11.975, 85.2285) -> (-12.975, 85.2285)
    line L15 (-14.0151, 48.5877) -> (-15.0151, 48.5877)
    line L16 (-20.225, 48.5877) -> (-21.225, 48.5877)
    distance L1 E3 = 1
    distance L5 E6 = 1
    coincidence: P1 E1, P2 E4, P5 E7, P6 E8, P7 P8
    parallelism: L1 E2, L3 L1, L5 E5
    horizontal: L2 H, L4 H, L6 H, L8 H, L13 H, L14 H, L15 H, L16 H
    symmetry: P5 P10 V, P6 P11 V, L5 L9 V, P8 P12 V, P9 P13 V, L7 L10 V, P4 P16 E9, P3 P17 E9, L3 L11 E9, P2 P18 E9, P1 P19 E9, L1 L12 E9
  Pocket13: profile Sketch35, direction (0, 0.9743, -0.2252), length 0.5
  CircPattern15: of Pocket13, instances 4, angular step 90, axis from edge [ZX plane of AxisSystem1 | YZ plane of AxisSystem1]
  Sketch36 on face of CloseSurface4, origin (0, -33.1899, 7.6699), H (1, 0, 0), V (0, 0.2252, 0.9743)
    line L1 (-13.9053, 81.0968) -> (13.9053, 81.0968)
    point P1 (-13.9053, 81.0968)
    point P2 (13.9053, 81.0968)
    reference projected line E1 (-7.5, 80.0968) -> (7.5, 80.0968) from edge [face of CircPattern9 | face of CloseSurface4]
    reference projected line E2 (-12.975, 85.2285) -> (-21.225, 48.5877) from edge [face of CloseSurface4 | face of Pocket13 from Sketch35.L12]
    reference projected line E3 (21.225, 48.5877) -> (12.975, 85.2285) from edge [face of CloseSurface4 | face of Pocket13 from Sketch35.L1]
    line L2 (13.9053, 81.0968) -> (13.6801, 82.0968)
    reference projected line E4 (21.225, 48.5877) -> (12.975, 85.2285) from edge [face of CloseSurface4 | face of Pocket13 from Sketch35.L1]
    line L3 (-13.6801, 82.0968) -> (13.6801, 82.0968)
    point P3 (13.6801, 82.0968)
    point P4 (-13.6801, 82.0968)
    point P5 (-13.9053, 81.0968)
    line L4 (-13.9053, 81.0968) -> (-13.6801, 82.0968)
    distance L1 E1 = 1
    distance L1 L3 = 1
    horizontal: L1 H
    coincidence: P1 E2, P2 E3, P1 P5
    parallelism: L2 E4
    symmetry: P3 P4 V, P2 P5 V, L2 L4 V
  Pocket14: profile Sketch36, direction (0, 0.9743, -0.2252), length 0.5
  CircPattern16: of Pocket14, instances 4, angular step 90, axis from edge [ZX plane of AxisSystem1 | YZ plane of AxisSystem1]
  Fillet17: radius 0.3, on edge [face of CloseSurface2 | face of CloseSurface2] (x4)
  Fillet18: radius 0.5, on edge [face of Pad1 from Sketch1.L4 | face of Pad1 from Sketch1.L3]; edge [face of Fillet2 | face of Fillet2] (x4); edge [face of Pad1 from Sketch1.L1 | face of Pad1 from Sketch1.L4]; edge [face of Pad1 from Sketch1.L2 | face of Pad1 from Sketch1.L1]; edge [face of Pad1 from Sketch1.L3 | face of Pad1 from Sketch1.L2]
  Fillet19: radius 0.5, on edge [face of CloseSurface2 | face of Pocket2 from Sketch6.A1]; edge [face of Pad1 from Sketch1.L4 | face of Pocket2 from Sketch6.L3]; edge [face of Pocket2 from Sketch6.L3 | face of Fillet2]; edge [face of Pocket2 from Sketch6.L1 | face of Fillet2]; edge [face of Pad1 from Sketch1.L4 | face of Pocket2 from Sketch6.L1]
  Fillet20: radius 0.5, on edge [face of Pocket1 from Sketch5.A1 | face of CloseSurface2]; edge [face of Pocket1 from Sketch5.L1 | face of Fillet2] (x2); edge [face of Pocket1 from Sketch5.L1 | face of Pad1 from Sketch1.L1]; edge [face of Fillet2 | face of Pocket1 from Sketch5.L2] (x2); edge [face of Pad1 from Sketch1.L1 | face of Pocket1 from Sketch5.L2]; edge [face of Pocket2 from Sketch6.A1 | face of CloseSurface2]; edge [face of Pocket2 from Sketch6.L1 | face of Fillet2]; edge [face of Pocket2 from Sketch6.L1 | face of Pad1 from Sketch1.L2]; edge [face of Pad1 from Sketch1.L2 | face of Pocket2 from Sketch6.L3]; edge [face of Pocket2 from Sketch6.L3 | face of Fillet2]; edge [face of CloseSurface2 | face of Pocket1 from Sketch5.A1]; edge [face of Pad1 from Sketch1.L3 | face of Pocket1 from Sketch5.L1]; edge [face of Pad1 from Sketch1.L3 | face of Pocket1 from Sketch5.L2]
  Fillet21: radius 1, on start face of Pad1 (x4)
  Fillet22: radius 0.2, on edge [face of CloseSurface4 | face of CloseSurface4] (x4)
  Fillet23: radius 0.2, on edge [face of Fillet14 | face of CloseSurface4] (x2); edge [face of Pocket6 from Sketch26.L4 | face of CloseSurface4]; edge [face of CloseSurface4 | face of CircPattern9] (x2); edge [face of CloseSurface4 | face of Pocket6 from Sketch26.L4]; edge [face of Pocket6 from Sketch26.L3 | face of CircPattern9]; edge [face of CircPattern9 | face of Pocket6 from Sketch26.L3]; edge [face of CircPattern9 | face of Pocket6 from Sketch26.L4]; edge [face of Pocket6 from Sketch26.L4 | face of CircPattern9]
  Fillet24: radius 0.2, on edge [face of Pad7 from Sketch9.L1 | face of Pad7 from Sketch9.L4]; edge [face of Pad7 from Sketch9.L4 | face of Pad7 from Sketch9.L3]; edge [face of Pad7 from Sketch9.L2 | face of Pad7 from Sketch9.L1]; edge [face of Pad7 from Sketch9.L3 | face of Pad7 from Sketch9.L2]
  Fillet25: radius 0.2, on edge [face of Pad6 from Sketch8.L2 | face of Pad6 from Sketch8.L3]; edge [face of Pad6 from Sketch8.L4 | face of Pad6 from Sketch8.L3]; edge [face of Pad6 from Sketch8.L2 | face of Pad6 from Sketch8.L1]; edge [face of Pad6 from Sketch8.L1 | face of Pad6 from Sketch8.L4]
  Fillet26: radius 0.2, on start face of Pocket3; end face of Pocket3
  Fillet27: radius 0.15, on edge [face of Pad7 from Sketch9.L3 | start face of Pad7]; edge [face of Pad7 from Sketch9.L2 | start face of Pad7]; edge [face of Pad7 from Sketch9.L1 | start face of Pad7]; edge [face of Pad7 from Sketch9.L4 | start face of Pad7]
  Fillet28: radius 0.15, on face of Split6
  Fillet29: radius 0.15, on edge [face of CircPattern6 | face of Pad7 from Sketch9.L3]; edge [face of CircPattern6 | face of Pad7 from Sketch9.L2]; edge [face of CircPattern6 | face of Pad7 from Sketch9.L1]; edge [face of CircPattern6 | face of Pad7 from Sketch9.L4]
  Sketch37 on face of CloseSurface2, origin (0, -38.813, 21.6056), H (1, 0, 0), V (0, 0.4864, 0.8737)
    point P1 (-32.4822, -16.8886)
    point P2 (-40.5544, -7.7555)
    line L1 (-40.5544, -7.7555) -> (-37.1744, -11.5797)
    reference projected line E1 (-25.8693, 22.4371) -> (-28.4506, 17.13) from edge [face of CloseSurface2 | face of Pocket12 from Sketch34.L5]
    reference projected line E3 (-15.8722, 22.4371) -> (-32.8928, -17.8606) from edge [face of CloseSurface2 | face of Pocket8 from Sketch30.L6]
    line L2 (-40.0806, -6.7814) -> (-36.2677, -11.0956)
    point P3 (-40.0806, -6.7814)
    point P4 (-32.0507, -15.8669)
    reference projected line E4 (-15.8722, 22.4371) -> (-32.8928, -17.8606) from edge [face of CloseSurface2 | face of Pocket8 from Sketch30.L6]
    reference projected line E5 (-25.8693, 22.4371) -> (-28.4506, 17.13) from edge [face of CloseSurface2 | face of Pocket12 from Sketch34.L5]
    line L3 (-32.4822, -16.8886) -> (-32.0507, -15.8669)
    line L4 (-40.5544, -7.7555) -> (-40.0806, -6.7814)
    point P5 (-28.2213, -6.8005)
    line L5 (-28.2213, -6.8005) -> (-28.8395, -8.264)
    point P6 (-28.8395, -8.264)
    line L6 (-28.8395, -8.264) -> (-35.5869, -11.8658)
    point P7 (-44.9966, -16.8886)
    line L7 (-28.2213, -6.8005) -> (-36.2677, -11.0956)
    point P8 (-44.2519, -15.3576)
    line L8 (-44.9966, -16.8886) -> (-44.2519, -15.3576)
    point P9 (-36.2677, -11.0956)
    line L9 (-35.5869, -11.8658) -> (-32.0507, -15.8669)
    point P10 (-35.5869, -11.8658)
    point P11 (-37.1744, -11.5797)
    line L10 (-36.4937, -12.3498) -> (-32.4822, -16.8886)
    point P12 (-36.4937, -12.3498)
    line L11 (-37.1744, -11.5797) -> (-44.2519, -15.3576)
    line L12 (-36.4937, -12.3498) -> (-44.9966, -16.8886)
    point P13 (-40.0806, -6.7814)
    point P14 (44.2519, -15.3576)
    point P15 (44.9966, -16.8886)
    line L13 (44.9966, -16.8886) -> (44.2519, -15.3576)
    point P16 (37.1744, -11.5797)
    line L14 (37.1744, -11.5797) -> (44.2519, -15.3576)
    point P17 (36.4937, -12.3498)
    line L15 (36.4937, -12.3498) -> (44.9966, -16.8886)
    point P18 (32.4822, -16.8886)
    line L16 (36.4937, -12.3498) -> (32.4822, -16.8886)
    point P19 (32.0507, -15.8669)
    point P20 (35.5869, -11.8658)
    line L17 (35.5869, -11.8658) -> (32.0507, -15.8669)
    point P21 (28.8395, -8.264)
    line L18 (28.8395, -8.264) -> (35.5869, -11.8658)
    point P22 (36.2677, -11.0956)
    point P23 (28.2213, -6.8005)
    line L19 (28.2213, -6.8005) -> (36.2677, -11.0956)
    point P24 (40.0806, -6.7814)
    line L20 (40.0806, -6.7814) -> (36.2677, -11.0956)
    point P25 (40.5544, -7.7555)
    line L21 (40.5544, -7.7555) -> (37.1744, -11.5797)
    line L22 (40.5544, -7.7555) -> (40.0806, -6.7814)
    line L23 (28.2213, -6.8005) -> (28.8395, -8.264)
    line L24 (32.4822, -16.8886) -> (32.0507, -15.8669)
    distance L6 L7 = 1
    distance L1 L2 = 1
    coincidence: P2 E1, P1 E3, P4 E4, P3 E5, P5 L3, P7 L4, P8 L4, L2 L9, L7 P11, L6 P12, L1 L10, L7 L11, L6 L12, P13 L8, P3 P13
    parallelism: L5 L3, L8 L4
    fix: L6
